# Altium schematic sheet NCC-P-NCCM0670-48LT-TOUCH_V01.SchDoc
size A4; Organization: Altium Limited; Address1: L3, 12a Rodborough Rd; Address2: Frenchs Forest; Address3: NSW; Address4: Australia 2086; SheetNumber: 1; SheetTotal: 1
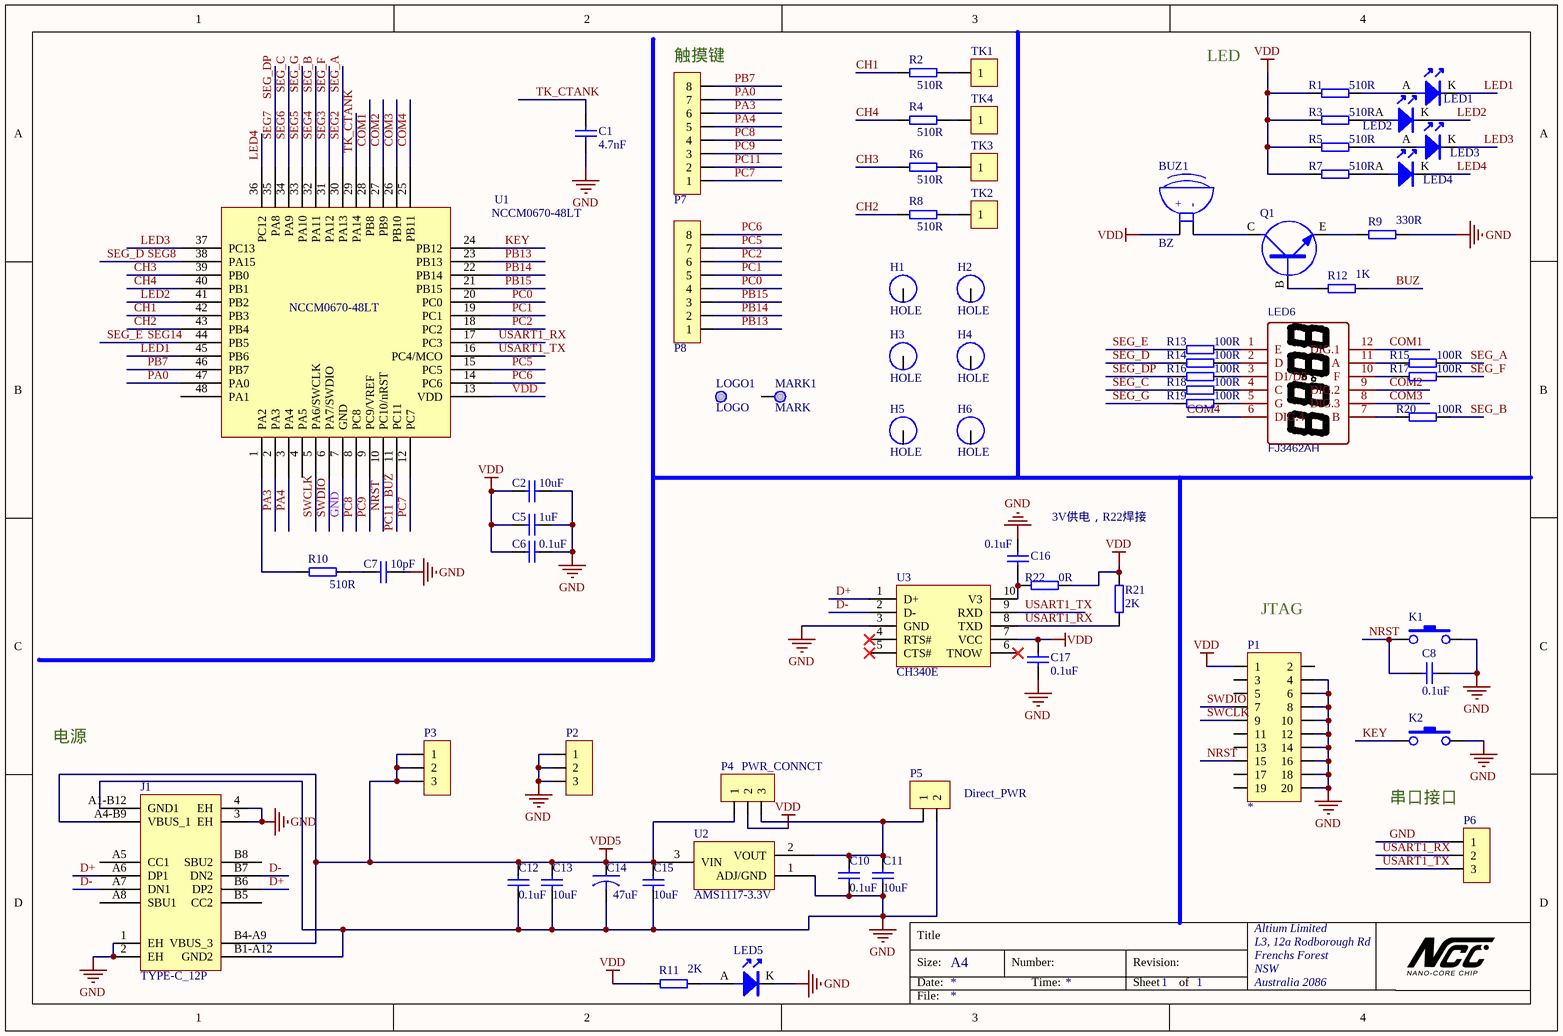
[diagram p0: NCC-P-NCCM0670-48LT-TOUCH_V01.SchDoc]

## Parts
BUZ1  产品型号: BZ  [BUZZER-D9P5-2P]  (hidden comment: BUZZER-SMD/DIP-2P)
C1  4.7nF  [0603C_0.6D]
C2  10uF  [0603C_0.6D]
C5  1uF  [0603C_0.6D]
C6  0.1uF  [0603C_0.6D]
C7  10pF  [0603C_0.6D]
C8  0.1uF  [0603C_0.6D]
C10  0.1uF  [0603C_0.6D]
C11  10uF  [0603C_0.6D]
C12  0.1uF  [0603C_0.6D]
C13  10uF  [0603C_0.6D]
C14  47uF  [CS-L6.6W6.6]
C15  10uF  [0603C_0.6D]
C16  0.1uF  [0603C_0.6D]
C17  0.1uF  [0603C_0.6D]
H1  HOLE  [Toolinghole-3]
H2  HOLE  [Toolinghole-3]
H3  HOLE  [Toolinghole-3]
H4  HOLE  [Toolinghole-3]
H5  HOLE  [Toolinghole-3]
H6  HOLE  [Toolinghole-3]
J1  TYPE-C_12P  [TYPE-C-12]
K1  BUTTON-2  [SW-6X3X2.5-2P-S]  (value not drawn)
K2  BUTTON-2  [SW-6X3X2.5-2P-S]  (value not drawn)
LED1  DIODE-LED  [D0603]  (value not drawn)
LED2  DIODE-LED  [D0603]  (value not drawn)
LED3  DIODE-LED  [D0603]  (value not drawn)
LED4  DIODE-LED  [D0603]  (value not drawn)
LED5  DIODE-LED  [D0603]  (value not drawn)
LED6  FJ3462AH  [LED-SEG-TH_12P-L30.0-W14.0-P2.54-S10.16-BL_FJ3462XH]
LOGO1  LOGO  [LOGO-NCC]
MARK1  MARK  [MARK-Single]
P1  HDR 20-D-M  [DC3 2.54_20]  (value not drawn)
P2  HDR 3-M  [SIP 2.54_3_S]  (value not drawn)
P3  HDR 3-M  [SIP 2.54_3_S]  (value not drawn)
P4  产品型号: PWR_CONNCT  [SIP 2.54_3_S]  (hidden comment: HDR 3-M)
P5  产品型号: Direct_PWR  [SIP 2.54_2_S]  (hidden comment: HDR 2-M)
P6  HDR 3-M  [SIP 2.54_3_S]  (value not drawn)
P7  HDR 8-M  [SIP 2.54_8_S]  (value not drawn)
P8  HDR 8-M  [SIP 2.54_8_S]  (value not drawn)
Q1  NPN  [SOT-23-3A]  (value not drawn)
R1  510R  [0603R_0.6D]
R2  510R  [0603R_0.6D]
R3  510R  [0603R_0.6D]
R4  510R  [0603R_0.6D]
R5  510R  [0603R_0.6D]
R6  510R  [0603R_0.6D]
R7  510R  [0603R_0.6D]
R8  510R  [0603R_0.6D]
R9  330R  [0603R_0.6D]
R10  510R  [0603R_0.6D]
R11  2K  [0603R_0.6D]
R12  1K  [0603R_0.6D]
R13  100R  [0603R_0.6D]
R14  100R  [0603R_0.6D]
R15  100R  [0603R_0.6D]
R16  100R  [0603R_0.6D]
R17  100R  [0603R_0.6D]
R18  100R  [0603R_0.6D]
R19  100R  [0603R_0.6D]
R20  100R  [0603R_0.6D]
R21  2K  [0603R_0.6D]
R22  0R  [0603R_0.6D]
TK1  HDR 1-M  [TOUCH_PAD_1.5/1.0]  (value not drawn)
TK2  HDR 1-M  [TOUCH_PAD_1.5/1.0]  (value not drawn)
TK3  HDR 1-M  [TOUCH_PAD_1.5/1.0]  (value not drawn)
TK4  HDR 1-M  [TOUCH_PAD_1.5/1.0]  (value not drawn)
U1  NCCM0670-48LT  [LQFP48(0.5)-7X7]
U2  AMS1117-3.3V  [SOT-223-4]
U3  CH340E  [MSOP10(0.5)-3x3]

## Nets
GND: C1.1 C2.2 C5.2 C6.2 C7.2 C8.1 C10.1 C11.1 C12.2 C13.2 C14.2 C15.1 C16.1 C17.2 J1.1(EH) J1.2(EH) J1.3(EH) J1.4(EH) J1.A1-B12(GND1) J1.B1-A12(GND2) K1.2 K2.2 LED5.K P1.4 P1.6 P1.8 P1.10 P1.12 P1.14 P1.16 P1.18 P1.20 P2.1 P2.2 P2.3 P5.2 P6.1 R9.1 U1.7(GND) U2.1(ADJ/GND) U3.3(GND)
VDD: BUZ1.1 C2.1 C5.1 C6.1 C17.1 P1.1 P4.2 R1.1 R3.1 R5.1 R7.1 R11.1 R21.1 R22.2 U1.13(VDD) U3.7(VCC)
VDD5: C12.1 C13.1 C14.1 C15.2 J1.A4-B9(VBUS_1) J1.B4-A9(VBUS_3) P3.1 P3.2 P3.3 P4.1 U2.3(VIN)
BUZ: P7.2 R12.1 U1.11(PC11)  [also labelled PC11]
CH1: R2.1 U1.42(PB3)
CH2: R8.1 U1.43(PB4)
CH3: R6.1 U1.39(PB0)
CH4: R4.1 U1.40(PB1)
COM1: LED6.12(DIG.1) U1.28(PB8)
COM2: LED6.9(DIG.2) U1.27(PB9)
COM3: LED6.8(DIG.3) U1.26(PB10)
COM4: LED6.6(DIG.4) U1.25(PB11)
D+: J1.A6(DP1) J1.B6(DP2) U3.1(D+)
D-: J1.A7(DN1) J1.B7(DN2) U3.2(D-)
KEY: K2.1 U1.24(PB12)
LED1: LED1.K U1.45(PB6)
LED2: LED2.K U1.41(PB2)
LED3: LED3.K U1.37(PC13)
LED4: LED4.K U1.36(PC12)
NRST: C8.2 K1.1 P1.15 U1.10(PC10/nRST)
PA0: P7.7 U1.47(PA0)
PA3: P7.6 U1.2(PA3)
PA4: P7.5 U1.3(PA4)
PB7: P7.8 U1.46(PB7)
PB13: P8.1 U1.23(PB13)
PB14: P8.2 U1.22(PB14)
PB15: P8.3 U1.21(PB15)
PC0: P8.4 U1.20(PC0)
PC1: P8.5 U1.19(PC1)
PC2: P8.6 U1.18(PC2)
PC5: P8.7 U1.15(PC5)
PC6: P8.8 U1.14(PC6)
PC7: P7.1 U1.12(PC7)
PC8: P7.4 U1.8(PC8)
PC9: P7.3 U1.9(PC9/VREF)
SEG2: R15.2 U1.30(PA13)  [also labelled SEG_A]
SEG3: R17.2 U1.31(PA12)  [also labelled SEG_F]
SEG4: R20.2 U1.32(PA11)  [also labelled SEG_B]
SEG5: R19.1 U1.33(PA10)  [also labelled SEG_G]
SEG6: R18.1 U1.34(PA9)  [also labelled SEG_C]
SEG7: R16.1 U1.35(PA8)  [also labelled SEG_DP]
SEG8: R14.1 U1.38(PA15)  [also labelled SEG_D]
SEG14: R13.1 U1.44(PB5)  [also labelled SEG_E]
SWCLK: P1.9 U1.5(PA6/SWCLK)
SWDIO: P1.7 U1.6(PA7/SWDIO)
TK_CTANK: C1.2 U1.29(PA14)
USART1_RX: P6.2 R21.2 U1.17(PC3) U3.8(TXD)
USART1_TX: P6.3 U1.16(PC4/MCO) U3.9(RXD)
NetBUZ1_2: BUZ1.2 Q1.C
NetC7_1: C7.1 R10.2
NetC10_2: C10.2 C11.2 P4.3 P5.1 U2.2(VOUT)
NetC16_2: C16.2 R22.1 U3.10(V3)
NetLED1_A: LED1.A R1.2
NetLED2_A: LED2.A R3.2
NetLED3_A: LED3.A R5.2
NetLED4_A: LED4.A R7.2
NetLED5_A: LED5.A R11.2
NetLED6_1: LED6.1(E) R13.2
NetLED6_2: LED6.2(D) R14.2
NetLED6_3: LED6.3(D1/D2) R16.2
NetLED6_4: LED6.4(C) R18.2
NetLED6_5: LED6.5(G) R19.2
NetLED6_7: LED6.7(B) R20.1
NetLED6_10: LED6.10(F) R17.1
NetLED6_11: LED6.11(A) R15.1
NetQ1_B: Q1.B R12.2
NetQ1_E: Q1.E R9.2
NetR2_2: R2.2 TK1.1
NetR4_2: R4.2 TK4.1
NetR6_2: R6.2 TK3.1
NetR8_2: R8.2 TK2.1
NetR10_1: R10.1 U1.1(PA2)

Not connected (* = marked no-connect by the designer): H1 1(H); H2 1(H); H3 1(H); H4 1(H); H5 1(H); H6 1(H); J1 A5(CC1) A8(SBU1) B5(CC2) B8(SBU2); MARK1 1; P1 2 3 5 11 13 17 19; U1 4(PA5) 48(PA1); U3 4(RTS#)* 5(CTS#)* 6(TNOW)*

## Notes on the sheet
- (near P7) 触摸键
- LED
- 3V供电，R22焊接
- (near P1) JTAG
- 电源
- 串口接口

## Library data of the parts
BUZ1 = BUZZER-SMD/DIP-2P: 蜂鸣器
C1 C2 C5-C8 C10-C13 C15-C17 = CAP-NP
C14 = CAP-P
H1-H6 = HOLE: 定位孔
J1 = TYPE-C_12P: C136423
K1 K2 = BUTTON-2: 轻触开关
LED1-LED4 = DIODE-LED: 白灯
LED5 = DIODE-LED: 红灯
LED6 = FJ3462AH: BOM_Manufacturer: Shenzhen Zhihao Elec; Contributor: LCSC
P1 = HDR 20-D-M: 公头
P2-P4 P6 = HDR 3-M: 公头
P5 = HDR 2-M: 公头
P7 P8 = HDR 8-M: 公头
R1-R22 = RES
TK1-TK4 = HDR 1-M: C3015094
U2 = AMS1117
